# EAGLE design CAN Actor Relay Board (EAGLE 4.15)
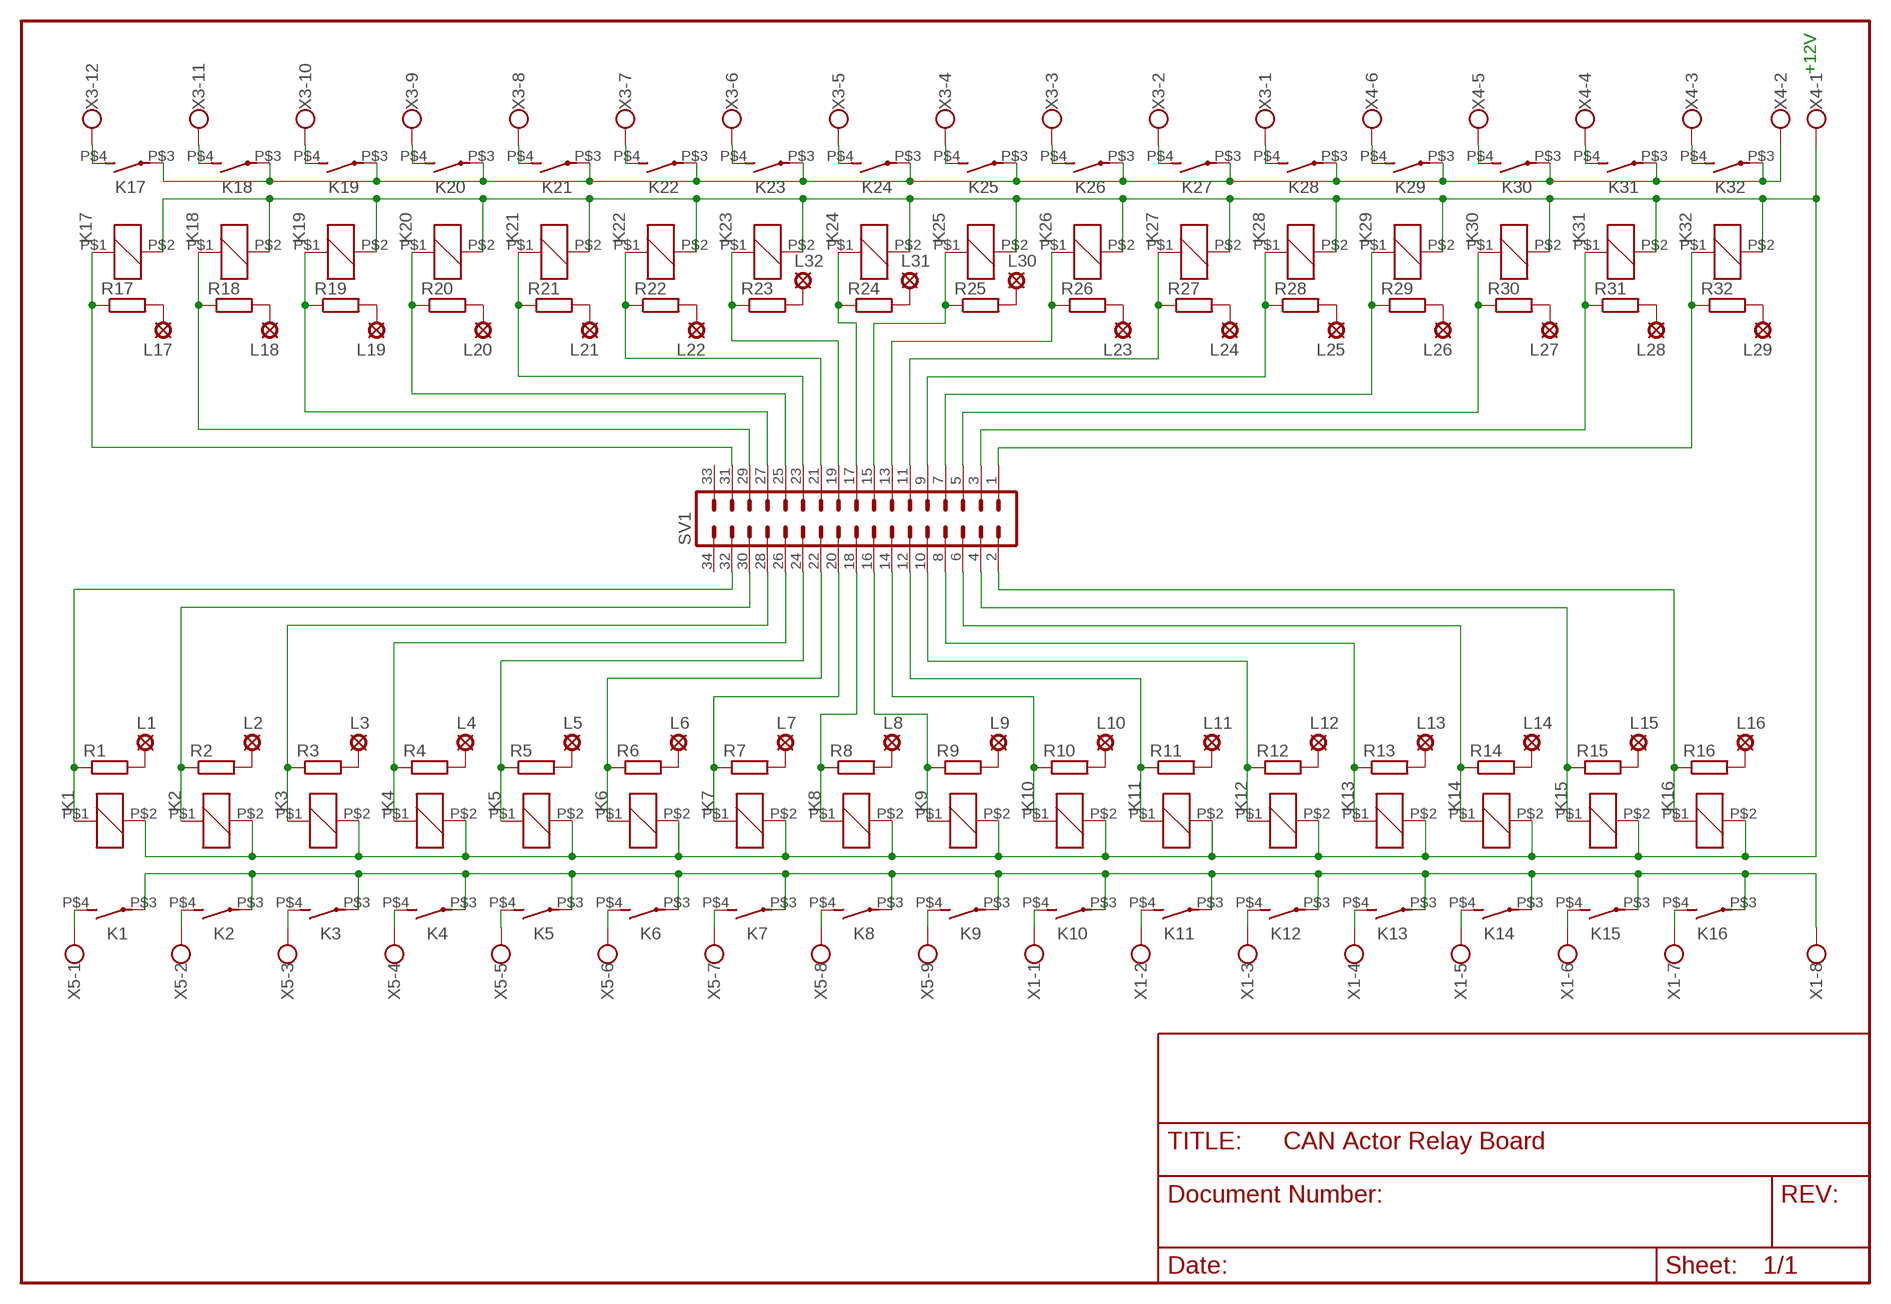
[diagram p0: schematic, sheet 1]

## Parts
K1  PE10  [PE-FORM-RICK]
K2  PE10  [PE-FORM-RICK]
K3  PE10  [PE-FORM-RICK]
K4  PE10  [PE-FORM-RICK]
K5  PE10  [PE-FORM-RICK]
K6  PE10  [PE-FORM-RICK]
K7  PE10  [PE-FORM-RICK]
K8  PE10  [PE-FORM-RICK]
K9  PE10  [PE-FORM-RICK]
K10  PE10  [PE-FORM-RICK]
K11  PE10  [PE-FORM-RICK]
K12  PE10  [PE-FORM-RICK]
K13  PE10  [PE-FORM-RICK]
K14  PE10  [PE-FORM-RICK]
K15  PE10  [PE-FORM-RICK]
K16  PE10  [PE-FORM-RICK]
K17  PE10  [PE-FORM-RICK]
K18  PE10  [PE-FORM-RICK]
K19  PE10  [PE-FORM-RICK]
K20  PE10  [PE-FORM-RICK]
K21  PE10  [PE-FORM-RICK]
K22  PE10  [PE-FORM-RICK]
K23  PE10  [PE-FORM-RICK]
K24  PE10  [PE-FORM-RICK]
K25  PE10  [PE-FORM-RICK]
K26  PE10  [PE-FORM-RICK]
K27  PE10  [PE-FORM-RICK]
K28  PE10  [PE-FORM-RICK]
K29  PE10  [PE-FORM-RICK]
K30  PE10  [PE-FORM-RICK]
K31  PE10  [PE-FORM-RICK]
K32  PE10  [PE-FORM-RICK]
L1  LSP10  [LSP10]
L2  LSP10  [LSP10]
L3  LSP10  [LSP10]
L4  LSP10  [LSP10]
L5  LSP10  [LSP10]
L6  LSP10  [LSP10]
L7  LSP10  [LSP10]
L8  LSP10  [LSP10]
L9  LSP10  [LSP10]
L10  LSP10  [LSP10]
L11  LSP10  [LSP10]
L12  LSP10  [LSP10]
L13  LSP10  [LSP10]
L14  LSP10  [LSP10]
L15  LSP10  [LSP10]
L16  LSP10  [LSP10]
L17  LSP10  [LSP10]
L18  LSP10  [LSP10]
L19  LSP10  [LSP10]
L20  LSP10  [LSP10]
L21  LSP10  [LSP10]
L22  LSP10  [LSP10]
L23  LSP10  [LSP10]
L24  LSP10  [LSP10]
L25  LSP10  [LSP10]
L26  LSP10  [LSP10]
L27  LSP10  [LSP10]
L28  LSP10  [LSP10]
L29  LSP10  [LSP10]
L30  LSP10  [LSP10]
L31  LSP10  [LSP10]
L32  LSP10  [LSP10]
R1  R-EU_0204/2V  [0204V]
R2  R-EU_0204/2V  [0204V]
R3  R-EU_0204/2V  [0204V]
R4  R-EU_0204/2V  [0204V]
R5  R-EU_0204/2V  [0204V]
R6  R-EU_0204/2V  [0204V]
R7  R-EU_0204/2V  [0204V]
R8  R-EU_0204/2V  [0204V]
R9  R-EU_0204/2V  [0204V]
R10  R-EU_0204/2V  [0204V]
R11  R-EU_0204/2V  [0204V]
R12  R-EU_0204/2V  [0204V]
R13  R-EU_0204/2V  [0204V]
R14  R-EU_0204/2V  [0204V]
R15  R-EU_0204/2V  [0204V]
R16  R-EU_0204/2V  [0204V]
R17  R-EU_0204/2V  [0204V]
R18  R-EU_0204/2V  [0204V]
R19  R-EU_0204/2V  [0204V]
R20  R-EU_0204/2V  [0204V]
R21  R-EU_0204/2V  [0204V]
R22  R-EU_0204/2V  [0204V]
R23  R-EU_0204/2V  [0204V]
R24  R-EU_0204/2V  [0204V]
R25  R-EU_0204/2V  [0204V]
R26  R-EU_0204/2V  [0204V]
R27  R-EU_0204/2V  [0204V]
R28  R-EU_0204/2V  [0204V]
R29  R-EU_0204/2V  [0204V]
R30  R-EU_0204/2V  [0204V]
R31  R-EU_0204/2V  [0204V]
R32  R-EU_0204/2V  [0204V]
SV1  ML34  [ML34]
X1  W237-08P  [W237-8P]
X3  W237-12P  [W237-12P]
X4  W237-06P  [W237-6P]
X5  W237-09P  [W237-9P]

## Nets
N$1 [thick]: K1.P$4(2:S) X5.1
N$2 [thick]: K2.P$4(2:S) X5.2
N$3 [thick]: K3.P$4(2:S) X5.3
N$4 [thick]: K5.P$4(2:S) X5.5
N$5 [thick]: K6.P$4(2:S) X5.6
N$6 [thick]: K7.P$4(2:S) X5.7
N$7 [thick]: K8.P$4(2:S) X5.8
N$8 [thick]: K9.P$4(2:S) X5.9
N$9 [thick]: K10.P$4(2:S) X1.1
N$10 [thick]: K11.P$4(2:S) X1.2
N$11 [thick]: K12.P$4(2:S) X1.3
N$12 [thick]: K13.P$4(2:S) X1.4
N$13 [thick]: K14.P$4(2:S) X1.5
N$14 [thick]: K15.P$4(2:S) X1.6
N$15 [thick]: K16.P$4(2:S) X1.7
N$16 [thick]: K17.P$4(2:S) X3.12
N$17 [thick]: K1.P$3(2:P) K2.P$3(2:P) K3.P$3(2:P) K4.P$3(2:P) K5.P$3(2:P) K6.P$3(2:P) K7.P$3(2:P) K8.P$3(2:P) K9.P$3(2:P) K10.P$3(2:P) K11.P$3(2:P) K12.P$3(2:P) K13.P$3(2:P) K14.P$3(2:P) K15.P$3(2:P) K16.P$3(2:P) X1.8
N$18: K1.P$2 K2.P$2 K3.P$2 K4.P$2 K5.P$2 K6.P$2 K7.P$2 K8.P$2 K9.P$2 K10.P$2 K11.P$2 K12.P$2 K13.P$2 K14.P$2 K15.P$2 K16.P$2 K17.P$2 K18.P$2 K19.P$2 K20.P$2 K21.P$2 K22.P$2 K23.P$2 K24.P$2 K25.P$2 K26.P$2 K27.P$2 K28.P$2 K29.P$2 K30.P$2 K31.P$2 K32.P$2 X4.1
N$19: K16.P$1 R16.1 SV1.2
N$20: K1.P$1 R1.1 SV1.32
N$21: K2.P$1 R2.1 SV1.30
N$22: K3.P$1 R3.1 SV1.28
N$23: K4.P$1 R4.1 SV1.26
N$24: K5.P$1 R5.1 SV1.24
N$25: K6.P$1 R6.1 SV1.22
N$26: K7.P$1 R7.1 SV1.20
N$27: K15.P$1 R15.1 SV1.4
N$28: K14.P$1 R14.1 SV1.6
N$29: K13.P$1 R13.1 SV1.8
N$30: K12.P$1 R12.1 SV1.10
N$31: K11.P$1 R11.1 SV1.12
N$32: K10.P$1 R10.1 SV1.14
N$33: K8.P$1 R8.1 SV1.18
N$34: K9.P$1 R9.1 SV1.16
N$35 [thick]: K18.P$4(2:S) X3.11
N$36 [thick]: K19.P$4(2:S) X3.10
N$37 [thick]: K4.P$4(2:S) X5.4
N$38 [thick]: K20.P$4(2:S) X3.9
N$39 [thick]: K21.P$4(2:S) X3.8
N$40 [thick]: K22.P$4(2:S) X3.7
N$41 [thick]: K23.P$4(2:S) X3.6
N$42 [thick]: K24.P$4(2:S) X3.5
N$43 [thick]: K25.P$4(2:S) X3.4
N$44 [thick]: K26.P$4(2:S) X3.3
N$45 [thick]: K27.P$4(2:S) X3.2
N$46 [thick]: K28.P$4(2:S) X3.1
N$47 [thick]: K29.P$4(2:S) X4.6
N$48 [thick]: K30.P$4(2:S) X4.5
N$49 [thick]: K31.P$4(2:S) X4.4
N$50 [thick]: K32.P$4(2:S) X4.3
N$51 [thick]: K17.P$3(2:P) K18.P$3(2:P) K19.P$3(2:P) K20.P$3(2:P) K21.P$3(2:P) K22.P$3(2:P) K23.P$3(2:P) K24.P$3(2:P) K25.P$3(2:P) K26.P$3(2:P) K27.P$3(2:P) K28.P$3(2:P) K29.P$3(2:P) K30.P$3(2:P) K31.P$3(2:P) K32.P$3(2:P) X4.2
N$52: K17.P$1 R17.1 SV1.31
N$53: K18.P$1 R18.1 SV1.29
N$54: K19.P$1 R19.1 SV1.27
N$55: K20.P$1 R20.1 SV1.25
N$56: K21.P$1 R21.1 SV1.23
N$57: K22.P$1 R22.1 SV1.21
N$58: K23.P$1 R23.1 SV1.19
N$59: K24.P$1 R24.1 SV1.17
N$60: K25.P$1 R25.1 SV1.15
N$61: K26.P$1 R26.1 SV1.13
N$62: K27.P$1 R27.1 SV1.11
N$63: K28.P$1 R28.1 SV1.9
N$64: K29.P$1 R29.1 SV1.7
N$65: K30.P$1 R30.1 SV1.5
N$66: K31.P$1 R31.1 SV1.3
N$67: K32.P$1 R32.1 SV1.1
N$68: L1.MP R1.2
N$69: L2.MP R2.2
N$70: L3.MP R3.2
N$71: L5.MP R5.2
N$72: L4.MP R4.2
N$73: L6.MP R6.2
N$74: L7.MP R7.2
N$75: L8.MP R8.2
N$76: L9.MP R9.2
N$77: L10.MP R10.2
N$78: L11.MP R11.2
N$79: L12.MP R12.2
N$80: L13.MP R13.2
N$81: L14.MP R14.2
N$82: L15.MP R15.2
N$83: L16.MP R16.2
N$84: L17.MP R17.2
N$85: L18.MP R18.2
N$86: L19.MP R19.2
N$87: L20.MP R20.2
N$88: L21.MP R21.2
N$89: L22.MP R22.2
N$90: L23.MP R26.2
N$91: L24.MP R27.2
N$92: L25.MP R28.2
N$93: L26.MP R29.2
N$94: L27.MP R30.2
N$95: L28.MP R31.2
N$96: L29.MP R32.2
N$97: L30.MP R25.2
N$98: L31.MP R24.2
N$99: L32.MP R23.2
Unconnected: SV1.33 SV1.34

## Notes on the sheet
- +12V

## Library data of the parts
K1-K32 = relay:PE10?*: SLIM POWER Relay NAiS Source: http://www.mew-europe.com/.. en_ds_61122_0000.pdf
L1-L32 = solpad:LSP10: SOLDER PAD
R1-R32 = rcl:R-EU_: RESISTOR, European symbol
SV1 = con-harting-ml:ML34: HARTING
X1 = con-wago-508:W237-08P: WAGO SREW CLAMP
X3 = con-wago-508:W237-12P: WAGO SREW CLAMP
X4 = con-wago-508:W237-06P: WAGO SREW CLAMP
X5 = con-wago-508:W237-09P: WAGO SREW CLAMP

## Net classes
1 thick: width 3.556 mm

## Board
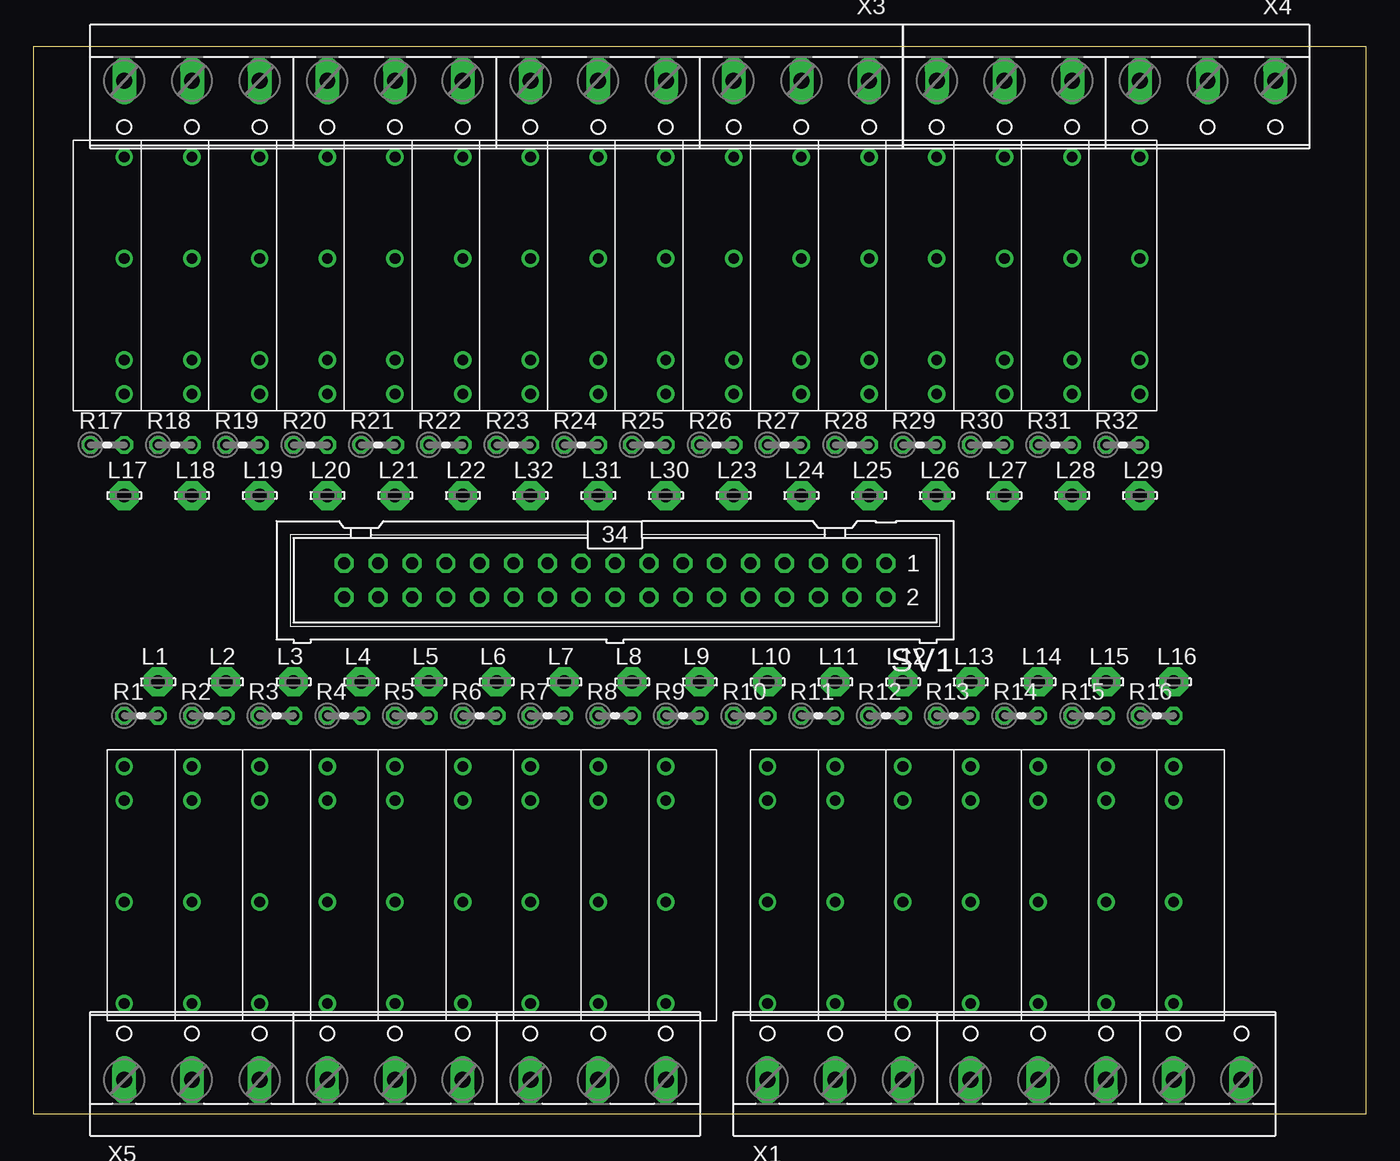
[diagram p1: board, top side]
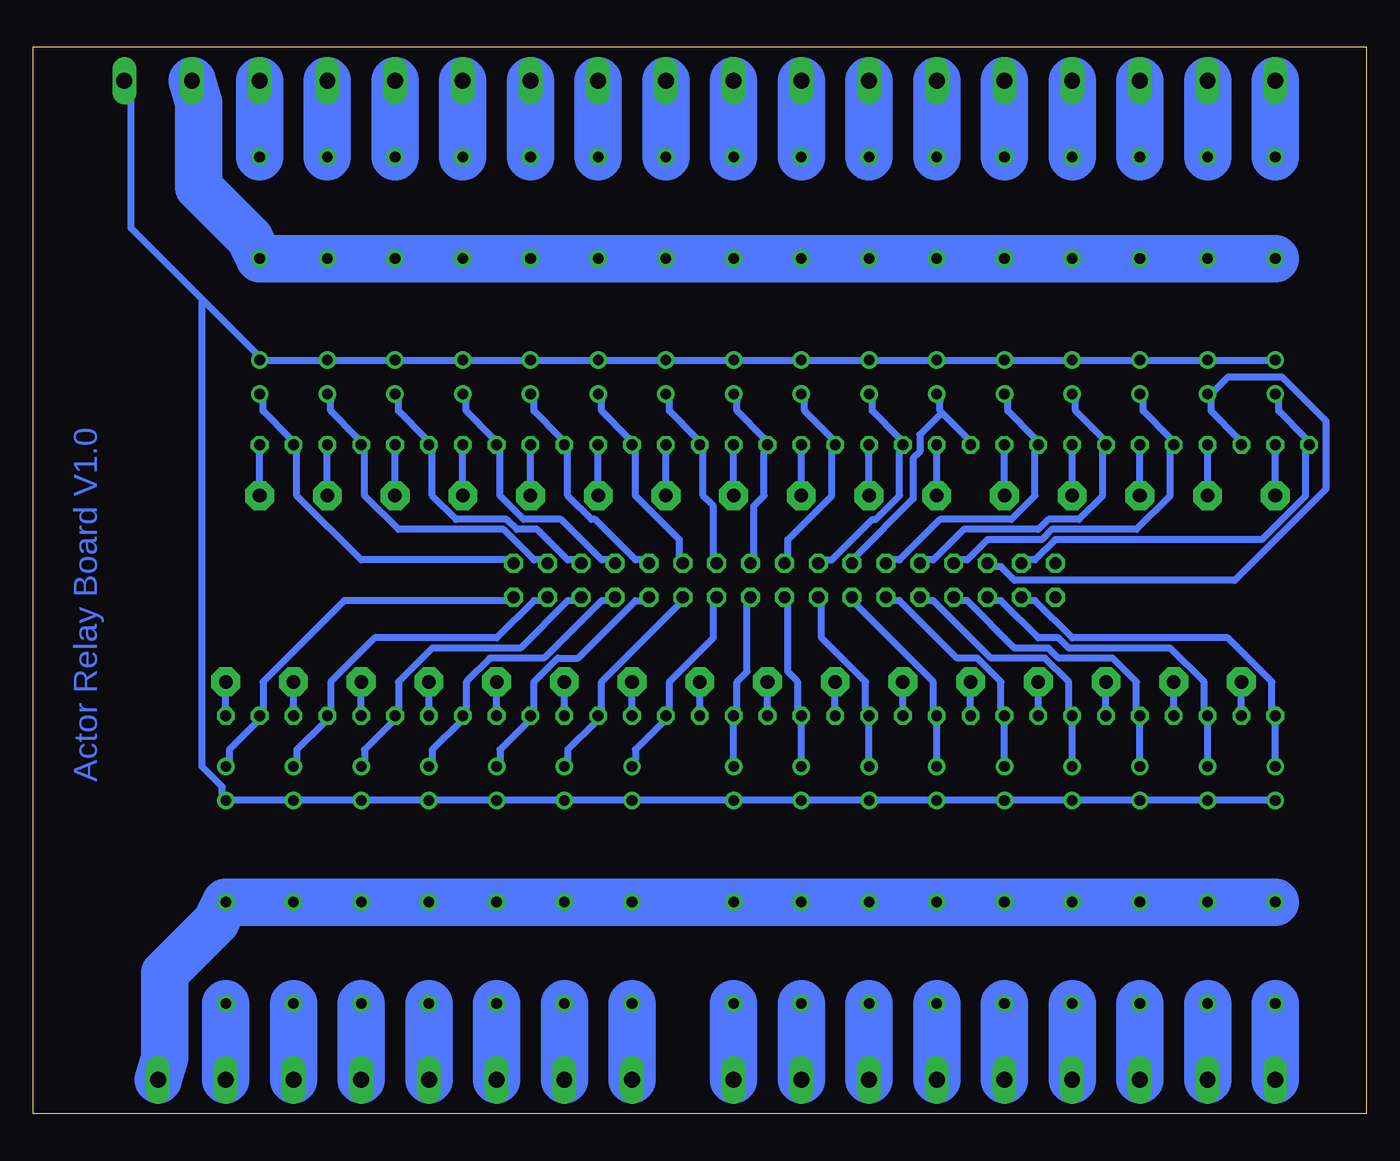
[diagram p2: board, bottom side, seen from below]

Size 100 x 80 mm. Coordinates in mm from the lower left corner, seen from the top.
Outline: 0,0 100,0 100,80 0,80 0,0
Copper layers (1*16): Top 0.035mm / dielectric 1.5mm / Bottom 0.035mm
Design rules "default": minimum track width 20mil, minimum drill 24mil, track to track 8mil, track to pad 8mil, pad to pad 8mil, via to via 8mil, smd to smd 8mil, copper to edge 40mil, drill to drill 8mil, minimum pad ring 10mil, minimum via ring 8mil, stop-mask expansion 4mil, vias tented up to drill 0mil, thermal gap 10mil

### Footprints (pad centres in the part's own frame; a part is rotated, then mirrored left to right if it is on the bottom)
PE-FORM-RICK = drill 0.8 round: P$1 -17.78,5.08; P$2 -15.24,5.08; P$3 -7.62,5.08; P$4 0,5.08
LSP10 = drill 1.016 pad 2.159 octagon: MP 0,0
0204V = drill 0.813 octagon: 1 -1.27,0; 2 1.27,0
ML34 = drill 0.914 octagon: 1 -20.32,-1.27; 2 -20.32,1.27; 3 -17.78,-1.27; 4 -17.78,1.27; 5 -15.24,-1.27; 6 -15.24,1.27; 7 -12.7,-1.27; 8 -12.7,1.27; 9 -10.16,-1.27; 10 -10.16,1.27; 11 -7.62,-1.27; 12 -7.62,1.27; 13 -5.08,-1.27; 14 -5.08,1.27; 15 -2.54,-1.27; 16 -2.54,1.27; 17 0,-1.27; 18 0,1.27; 19 2.54,-1.27; 20 2.54,1.27; 21 5.08,-1.27; 22 5.08,1.27; 23 7.62,-1.27; 24 7.62,1.27; 25 10.16,-1.27; 26 10.16,1.27; 27 12.7,-1.27; 28 12.7,1.27; 29 15.24,-1.27; 30 15.24,1.27; 31 17.78,-1.27; 32 17.78,1.27; 33 20.32,-1.27; 34 20.32,1.27
W237-8P = drill 1.194 long: 1 -17.78,-0.635; 2 -12.7,-0.635; 3 -7.62,-0.635; 4 -2.54,-0.635; 5 2.54,-0.635; 6 7.62,-0.635; 7 12.7,-0.635; 8 17.78,-0.635
W237-12P = drill 1.194 long: 1 -27.94,-0.635; 2 -22.86,-0.635; 3 -17.78,-0.635; 4 -12.7,-0.635; 5 -7.62,-0.635; 6 -2.54,-0.635; 7 2.54,-0.635; 8 7.62,-0.635; 9 12.7,-0.635; 10 17.78,-0.635; 11 22.86,-0.635; 12 27.94,-0.635
W237-6P = drill 1.194 long: 1 -12.7,-0.635; 2 -7.62,-0.635; 3 -2.54,-0.635; 4 2.54,-0.635; 5 7.62,-0.635; 6 12.7,-0.635
W237-9P = drill 1.194 long: 1 -20.32,-0.635; 2 -15.24,-0.635; 3 -10.16,-0.635; 4 -5.08,-0.635; 5 0,-0.635; 6 5.08,-0.635; 7 10.16,-0.635; 8 15.24,-0.635; 9 20.32,-0.635

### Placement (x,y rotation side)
K1  1.74,8.25 270 top
K2  6.82,8.25 270 top
K3  11.9,8.25 270 top
K4  16.98,8.25 270 top
K5  22.06,8.25 270 top
K6  27.14,8.25 270 top
K7  32.22,8.25 270 top
K8  37.3,8.25 270 top
K9  42.38,8.25 270 top
K10  50,8.25 270 top
K11  55.08,8.25 270 top
K12  60.16,8.25 270 top
K13  65.24,8.25 270 top
K14  70.32,8.25 270 top
K15  75.4,8.25 270 top
K16  80.48,8.25 270 top
K17  11.9,71.75 90 top
K18  16.98,71.75 90 top
K19  22.06,71.75 90 top
K20  27.14,71.75 90 top
K21  32.22,71.75 90 top
K22  37.3,71.75 90 top
K23  42.38,71.75 90 top
K24  47.46,71.75 90 top
K25  52.54,71.75 90 top
K26  57.62,71.75 90 top
K27  62.7,71.75 90 top
K28  67.78,71.75 90 top
K29  72.86,71.75 90 top
K30  77.94,71.75 90 top
K31  83.02,71.75 90 top
K32  88.1,71.75 90 top
L1  9.36,32.38 0 top
L2  14.44,32.38 0 top
L3  19.52,32.38 0 top
L4  24.6,32.38 0 top
L5  29.68,32.38 0 top
L6  34.76,32.38 0 top
L7  39.84,32.38 0 top
L8  44.92,32.38 0 top
L9  50,32.38 0 top
L10  55.08,32.38 0 top
L11  60.16,32.38 0 top
L12  65.24,32.38 0 top
L13  70.32,32.38 0 top
L14  75.4,32.38 0 top
L15  80.48,32.38 0 top
L16  85.56,32.38 0 top
L17  6.82,46.35 0 top
L18  11.9,46.35 0 top
L19  16.98,46.35 0 top
L20  22.06,46.35 0 top
L21  27.14,46.35 0 top
L22  32.22,46.35 0 top
L23  52.54,46.35 0 top
L24  57.62,46.35 0 top
L25  62.7,46.35 0 top
L26  67.78,46.35 0 top
L27  72.86,46.35 0 top
L28  77.94,46.35 0 top
L29  83.02,46.35 0 top
L30  47.46,46.35 0 top
L31  42.38,46.35 0 top
L32  37.3,46.35 0 top
R1  8.09,29.84 0 top
R2  13.17,29.84 0 top
R3  18.25,29.84 0 top
R4  23.33,29.84 0 top
R5  28.41,29.84 0 top
R6  33.49,29.84 0 top
R7  38.57,29.84 0 top
R8  43.65,29.84 0 top
R9  48.73,29.84 0 top
R10  53.81,29.84 0 top
R11  58.89,29.84 0 top
R12  63.97,29.84 0 top
R13  69.05,29.84 0 top
R14  74.13,29.84 0 top
R15  79.21,29.84 0 top
R16  84.29,29.84 0 top
R17  5.55,50.16 0 top
R18  10.63,50.16 0 top
R19  15.71,50.16 0 top
R20  20.79,50.16 0 top
R21  25.87,50.16 0 top
R22  30.95,50.16 0 top
R23  36.03,50.16 0 top
R24  41.11,50.16 0 top
R25  46.19,50.16 0 top
R26  51.27,50.16 0 top
R27  56.35,50.16 0 top
R28  61.43,50.16 0 top
R29  66.51,50.16 0 top
R30  71.59,50.16 0 top
R31  76.67,50.16 0 top
R32  81.75,50.16 0 top
SV1  43.65,40 180 top
X1  72.86,3.17 0 top
X3  34.76,76.83 180 top
X4  80.48,76.83 180 top
X5  27.14,3.17 0 top

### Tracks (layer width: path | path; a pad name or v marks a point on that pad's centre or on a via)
N$1
  Bottom 3.556: X5.1 K1.P$4
N$2
  Bottom 3.556: X5.2 K2.P$4
N$3
  Bottom 3.556: X5.3 K3.P$4
N$4
  Bottom 3.556: X5.5 K5.P$4
N$5
  Bottom 3.556: X5.6 K6.P$4
N$6
  Bottom 3.556: X5.7 K7.P$4
N$7
  Bottom 3.556: X5.8 K8.P$4
N$8
  Bottom 3.556: X5.9 K9.P$4
N$9
  Bottom 3.556: X1.1 K10.P$4
N$10
  Bottom 3.556: X1.2 K11.P$4
N$11
  Bottom 3.556: X1.3 K12.P$4
N$12
  Bottom 3.556: X1.4 K13.P$4
N$13
  Bottom 3.556: X1.5 K14.P$4
N$14
  Bottom 3.556: X1.6 K15.P$4
N$15
  Bottom 3.556: X1.7 K16.P$4
N$16
  Bottom 3.556: K17.P$4 X3.12
N$17
  Bottom 3.556: K1.P$3 K2.P$3 K3.P$3 K4.P$3 K5.P$3 K6.P$3 K7.P$3 K8.P$3 K9.P$3 K10.P$3 K11.P$3 K12.P$3 K13.P$3 K14.P$3 K15.P$3 K16.P$3 86.32,14.35 90.13,10.54 90.13,4.19 X1.8
N$18
  Bottom 0.508: K1.P$2 K2.P$2 K3.P$2 K4.P$2 K5.P$2 K6.P$2 K7.P$2 K8.P$2 K9.P$2 K10.P$2 K11.P$2 K12.P$2 K13.P$2 K14.P$2 K15.P$2 K16.P$2 85.81,24 85.81,24.51 87.34,26.03 87.34,60.83 87.21,60.96 | 87.21,60.96 83.27,57.02 K32.P$2 K31.P$2 K30.P$2 K29.P$2 K28.P$2 K27.P$2 K26.P$2 K25.P$2 K24.P$2 K23.P$2 K22.P$2 K21.P$2 K20.P$2 K19.P$2 K18.P$2 K17.P$2 | 87.21,60.96 92.67,66.42 92.67,75.81 X4.1
N$19
  Bottom 0.508: K16.P$1 85.31,26.54 85.31,27.3 83.27,29.33 R16.1 82.77,30.35 82.77,32.38 76.67,38.48 64.48,38.48 SV1.2
N$20
  Bottom 0.508: K1.P$1 R1.1 7.07,30.35 7.07,32.38 10.38,35.68 22.06,35.68 24.85,38.48 25.36,38.48 SV1.32
N$21
  Bottom 0.508: K2.P$1 R2.1 12.15,30.35 12.15,32.38 14.69,34.92 22.31,34.92 23.08,35.68 24.6,35.68 27.39,38.48 27.9,38.48 SV1.30
N$22
  Bottom 0.508: K3.P$1 R3.1 17.23,30.35 17.23,32.38 19.01,34.16 23.08,34.16 23.84,34.92 26.38,34.92 29.93,38.48 30.44,38.48 SV1.28
N$23
  Bottom 0.508: K4.P$1 R4.1 22.31,30.35 22.31,32.38 24.09,34.16 28.16,34.16 32.47,38.48 32.98,38.48 SV1.26
N$24
  Bottom 0.508: K5.P$1 R5.1 27.39,30.35 27.39,32.38 29.17,34.16 30.7,34.16 35.01,38.48 35.52,38.48 SV1.24
N$25
  Bottom 0.508: K6.P$1 R6.1 32.47,30.35 32.47,32.38 38.32,38.22 SV1.22
N$26
  Bottom 0.508: K7.P$1 R7.1 37.55,30.35 37.55,32.38 40.86,35.68 40.86,38.22 SV1.20
N$27
  Bottom 0.508: K15.P$1 80.23,26.54 80.23,27.3 78.19,29.33 R15.1 77.69,30.35 77.69,32.38 74.38,35.68 65.24,35.68 62.45,38.48 61.94,38.48 SV1.4
N$28
  Bottom 0.508: K14.P$1 75.15,26.54 75.15,27.3 73.11,29.33 R14.1 72.61,30.35 72.61,32.38 70.07,34.92 63.46,34.92 59.91,38.48 59.4,38.48 SV1.6
N$29
  Bottom 0.508: K13.P$1 70.07,26.54 70.07,27.3 68.03,29.33 R13.1 67.53,30.35 67.53,32.38 65.75,34.16 61.68,34.16 57.37,38.48 56.86,38.48 SV1.8
N$30
  Bottom 0.508: K12.P$1 64.99,26.54 64.99,27.3 62.95,29.33 R12.1 62.45,30.35 62.45,32.38 60.67,34.16 59.14,34.16 54.83,38.48 54.32,38.48 SV1.10
N$31
  Bottom 0.508: K11.P$1 59.91,26.54 59.91,27.3 57.87,29.33 R11.1 57.37,30.35 57.37,32.38 51.52,38.22 SV1.12
N$32
  Bottom 0.508: K10.P$1 54.83,26.54 54.83,27.3 52.79,29.33 R10.1 52.29,30.35 52.29,32.38 48.98,35.68 48.98,38.22 SV1.14
N$33
  Bottom 0.508: K8.P$1 R8.1 42.63,30.35 42.63,32.38 43.4,33.14 43.4,38.22 SV1.18
N$34
  Bottom 0.508: K9.P$1 R9.1 47.21,30.35 47.21,32.38 46.44,33.14 46.44,38.22 SV1.16
N$35
  Bottom 3.556: K18.P$4 X3.11
N$36
  Bottom 3.556: K19.P$4 X3.10
N$37
  Bottom 3.556: X5.4 K4.P$4
N$38
  Bottom 3.556: K20.P$4 X3.9
N$39
  Bottom 3.556: K21.P$4 X3.8
N$40
  Bottom 3.556: K22.P$4 X3.7
N$41
  Bottom 3.556: K23.P$4 X3.6
N$42
  Bottom 3.556: K24.P$4 X3.5
N$43
  Bottom 3.556: K25.P$4 X3.4
N$44
  Bottom 3.556: K26.P$4 X3.3
N$45
  Bottom 3.556: K27.P$4 X3.2
N$46
  Bottom 3.556: K28.P$4 X3.1
N$47
  Bottom 3.556: K29.P$4 X4.6
N$48
  Bottom 3.556: K30.P$4 X4.5
N$49
  Bottom 3.556: K31.P$4 X4.4
N$50
  Bottom 3.556: K32.P$4 X4.3
N$51
  Bottom 3.556: K17.P$3 K18.P$3 K19.P$3 K20.P$3 K21.P$3 K22.P$3 K23.P$3 K24.P$3 K25.P$3 K26.P$3 K27.P$3 K28.P$3 K29.P$3 K30.P$3 K31.P$3 K32.P$3 83.78,65.65 87.59,69.46 87.59,75.81 X4.2
N$52
  Bottom 0.508: K17.P$1 6.57,53.46 6.57,52.7 4.53,50.67 R17.1 4.53,49.65 4.53,46.35 7.84,43.05 23.33,43.05 24.85,41.52 25.36,41.52 SV1.31
N$53
  Bottom 0.508: R18.1 9.61,50.67 11.65,52.7 11.65,53.46 K18.P$1 11.39,54.22 10.38,55.24 6.31,55.24 3.01,51.94 3.01,46.86 9.87,40 26.38,40 27.39,41.02 27.9,41.02 SV1.29
N$54
  Bottom 0.508: K19.P$1 16.73,53.46 16.73,52.7 14.69,50.67 R19.1 14.69,49.65 14.69,46.35 17.23,43.81 23.58,43.81 24.35,43.05 28.41,43.05 29.93,41.52 30.44,41.52 SV1.27
N$55
  Bottom 0.508: K20.P$1 21.81,53.46 21.81,52.7 19.77,50.67 R20.1 19.77,49.65 19.77,46.35 21.55,44.57 23.84,44.57 24.6,43.81 30.19,43.81 32.47,41.52 32.98,41.52 SV1.25
N$56
  Bottom 0.508: K21.P$1 26.89,53.46 26.89,52.7 24.85,50.67 R21.1 24.85,49.65 24.85,46.35 26.63,44.57 31.97,44.57 35.01,41.52 35.52,41.52 SV1.23
N$57
  Bottom 0.508: 31.84,52.57 29.93,50.67 R22.1 | 31.84,52.57 31.97,52.7 31.97,53.46 K22.P$1 | SV1.21 38.32,41.78 34,46.1 34,49.14 33.49,49.65 33.49,50.92 31.84,52.57
N$58
  Bottom 0.508: K23.P$1 37.05,53.46 37.05,52.7 35.01,50.67 R23.1 35.01,49.65 35.01,46.35 36.79,44.57 37.05,44.57 40.09,41.52 40.6,41.52 SV1.19
N$59
  Bottom 0.508: K24.P$1 42.13,53.46 42.13,52.7 40.09,50.67 R24.1 40.09,49.65 40.09,46.35 43.4,43.05 43.4,41.78 SV1.17
N$60
  Bottom 0.508: K25.P$1 47.21,53.46 47.21,52.7 45.17,50.67 R25.1 45.17,49.65 45.17,46.35 45.94,45.59 45.94,41.78 SV1.15
N$61
  Bottom 0.508: K26.P$1 52.29,53.46 52.29,52.7 50.25,50.67 R26.1 49.75,49.65 49.75,46.35 48.98,45.59 48.98,41.78 SV1.13
N$62
  Bottom 0.508: K27.P$1 57.37,53.46 57.37,52.7 55.33,50.67 R27.1 54.83,49.65 54.83,46.35 51.52,43.05 51.52,41.78 SV1.11
N$63
  Bottom 0.508: K28.P$1 62.45,53.46 62.45,52.7 60.41,50.67 R28.1 59.91,49.65 59.91,46.35 58.13,44.57 57.87,44.57 54.83,41.52 54.32,41.52 SV1.9
N$64
  Bottom 0.508: K29.P$1 67.53,53.46 67.53,52.7 65.49,50.67 R29.1 64.99,49.65 64.99,46.35 63.21,44.57 60.41,44.57 57.37,41.52 56.86,41.52 SV1.7
N$65
  Bottom 0.508: K30.P$1 72.61,53.46 72.61,52.7 70.57,50.67 R30.1 70.07,49.65 70.07,46.35 68.29,44.57 64.48,44.57 63.72,43.81 62.19,43.81 59.91,41.52 59.4,41.52 SV1.5
N$66
  Bottom 0.508: K31.P$1 77.69,53.46 77.69,52.7 75.65,50.67 R31.1 75.15,49.65 75.15,46.35 72.61,43.81 64.73,43.81 62.45,41.52 61.94,41.52 SV1.3
N$67
  Bottom 0.508: K32.P$1 82.77,53.46 82.77,52.7 80.73,50.67 R32.1 80.23,49.65 80.23,46.35 75.4,41.52 64.48,41.52 SV1.1
N$68
  Bottom 0.508: R1.2 L1.MP
N$69
  Bottom 0.508: R2.2 L2.MP
N$70
  Bottom 0.508: R3.2 L3.MP
N$71
  Bottom 0.508: R5.2 L5.MP
N$72
  Bottom 0.508: R4.2 L4.MP
N$73
  Bottom 0.508: R6.2 L6.MP
N$74
  Bottom 0.508: R7.2 L7.MP
N$75
  Bottom 0.508: R8.2 L8.MP
N$76
  Bottom 0.508: R9.2 L9.MP
N$77
  Bottom 0.508: R10.2 L10.MP
N$78
  Bottom 0.508: R11.2 L11.MP
N$79
  Bottom 0.508: R12.2 L12.MP
N$80
  Bottom 0.508: R13.2 L13.MP
N$81
  Bottom 0.508: R14.2 L14.MP
N$82
  Bottom 0.508: R15.2 L15.MP
N$83
  Bottom 0.508: R16.2 L16.MP
N$84
  Bottom 0.508: L17.MP R17.2
N$85
  Bottom 0.508: L18.MP R18.2
N$86
  Bottom 0.508: L19.MP R19.2
N$87
  Bottom 0.508: L20.MP R20.2
N$88
  Bottom 0.508: L21.MP R21.2
N$89
  Bottom 0.508: L22.MP R22.2
N$90
  Bottom 0.508: L23.MP R26.2
N$91
  Bottom 0.508: L24.MP R27.2
N$92
  Bottom 0.508: L25.MP R28.2
N$93
  Bottom 0.508: L26.MP R29.2
N$94
  Bottom 0.508: L27.MP R30.2
N$95
  Bottom 0.508: L28.MP R31.2
N$96
  Bottom 0.508: L29.MP R32.2
N$97
  Bottom 0.508: L30.MP R25.2
N$98
  Bottom 0.508: L31.MP R24.2
N$99
  Bottom 0.508: L32.MP R23.2

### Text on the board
Bottom: Actor Relay Board V1.0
